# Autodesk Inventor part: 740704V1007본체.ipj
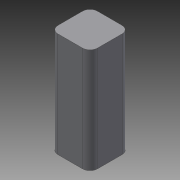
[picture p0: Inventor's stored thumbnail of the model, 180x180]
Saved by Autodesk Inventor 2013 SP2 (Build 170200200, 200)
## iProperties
Created: 2024-07
Part Number: 740704V1007본체.ipj
Material: Generic
Document SubType Name: Modeling
Designer: a
Density: 1 g/cm^3
Author: a
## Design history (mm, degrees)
sketch "스케치1"
  geometry: L1 (-25, 40)-(25, 40); L2 (40, 25)-(40, -25); L3 (25, -40)-(-25, -40); L4 (-40, -25)-(-40, 25); L5 (-40, 40)-(40, -40); L6 (40, 40)-(-40, -40); A1 r 15 centre (-25, 25) between (-25, 40) and (-40, 25); A2 r 15 centre (25, 25) between (40, 25) and (25, 40); A3 r 15 centre (-25, -25) between (-40, -25) and (-25, -40); A4 r 15 centre (25, -25) between (25, -40) and (40, -25); 1 further point
  constraints: 12 end point, 8 point on circle, 8 point on line, 8 tangent, 4 centre point, 3 equal radius, 2 midpoint, 2 parallel, 1 horizontal, 1 perpendicular
  dimensions: "d0" = 80 distance of L5.start L6.start; "d2" = 80 distance of L6.start L5.end; "d3" = 15 radius of A1
extrude "돌출1" new body sketch "스케치1" stored distance "d4" = 212; taper "d5" = 0 deg
node "솔리드1"
